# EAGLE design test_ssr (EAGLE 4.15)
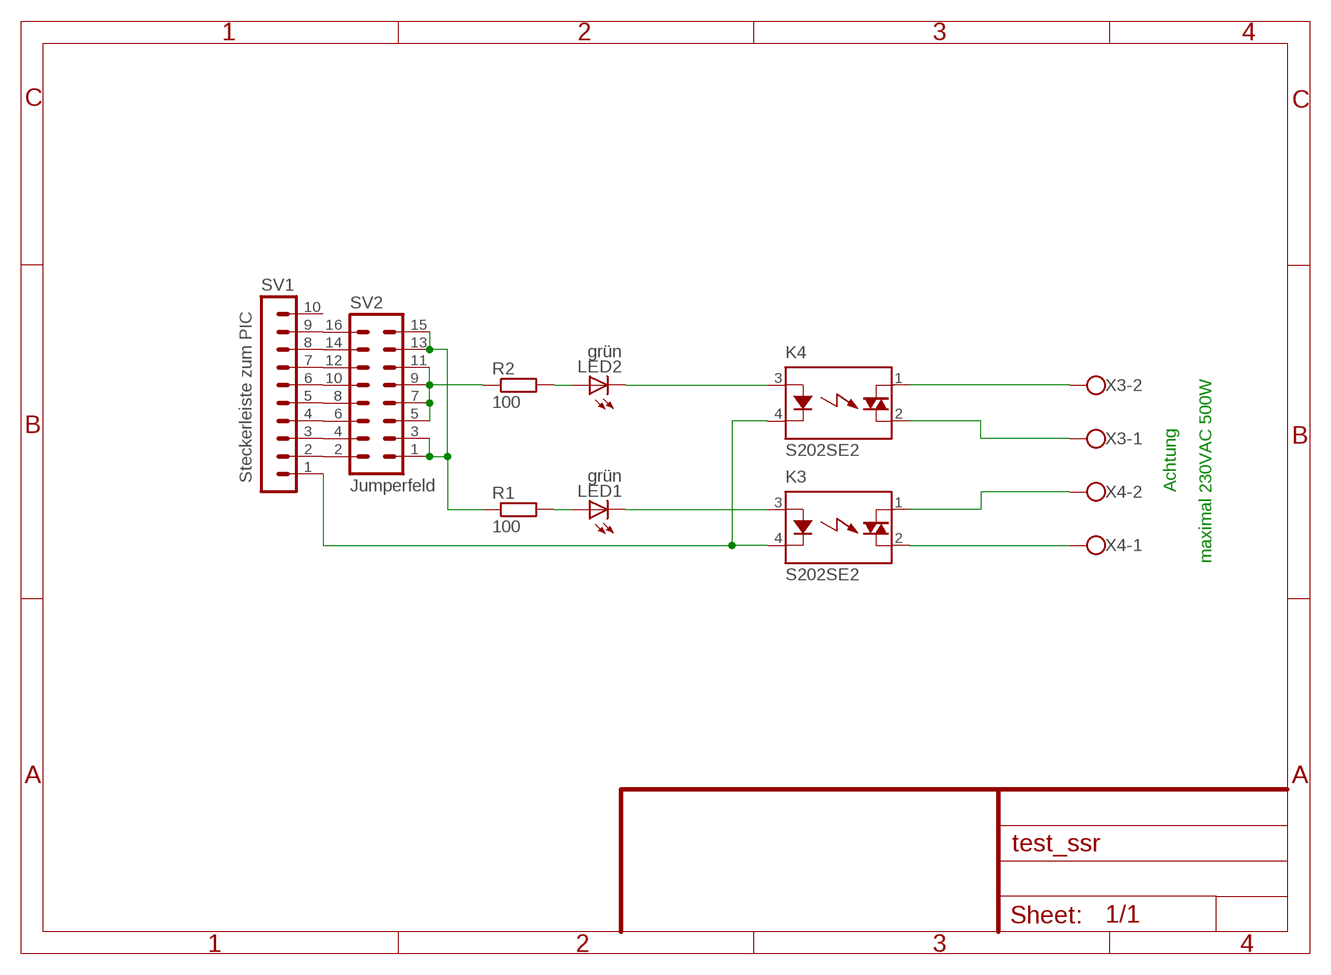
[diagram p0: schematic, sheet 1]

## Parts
K3  S202SE2  [S2XXEX]
K4  S202SE2  [S2XXEX]
LED1  grün  LED3MM  [LED3MM]
LED2  grün  LED3MM  [LED3MM]
R1  100  R-EU_0207/10  [0207/10]
R2  100  R-EU_0207/10  [0207/10]
SV1  Steckerleiste zum PIC  MA10-1W  [MA10-1W]
SV2  Jumperfeld  MA08-2  [MA08-2]
X3  W237-102  [W237-102]
X4  W237-102  [W237-102]

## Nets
GND: K3.4(K) K4.4(K) SV1.1
N$1: SV1.2 SV2.2
N$2: SV1.3 SV2.4
N$3: SV1.4 SV2.6
N$4: SV1.5 SV2.8
N$5: SV1.6 SV2.10
N$6: SV1.7 SV2.12
N$7: SV1.8 SV2.14
N$8: SV1.9 SV2.16
N$9: R1.1 SV2.1 SV2.3 SV2.13 SV2.15
N$10: R2.1 SV2.5 SV2.7 SV2.9 SV2.11
N$11: K4.2(DS2) X3.1
N$12: K4.3(A) LED2.K(C)
N$13: K3.3(A) LED1.K(C)
N$15: LED2.A R2.2
N$16: LED1.A R1.2
N$18: K4.1(DS1) X3.2
N$24: K3.1(DS1) X4.2
N$25: K3.2(DS2) X4.1
Unconnected: SV1.10

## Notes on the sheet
- Achtung
- maximal 230VAC 500W

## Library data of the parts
K3 K4 = relay:S2*: SIP Type SSR for Medium Power Control SHARP Source: 168149-da-01-en-Solid_State_Relais_S_202_SE1_SE2.pdf
LED1 LED2 = led:LED: LED
R1 R2 = rcl:R-EU_: RESISTOR, European symbol
SV1 = con-lstb:MA10-1W: PIN HEADER
SV2 = con-lstb:MA08-2: PIN HEADER
X3 X4 = con-wago-500:W237-102: WAGO SCREW CLAMP

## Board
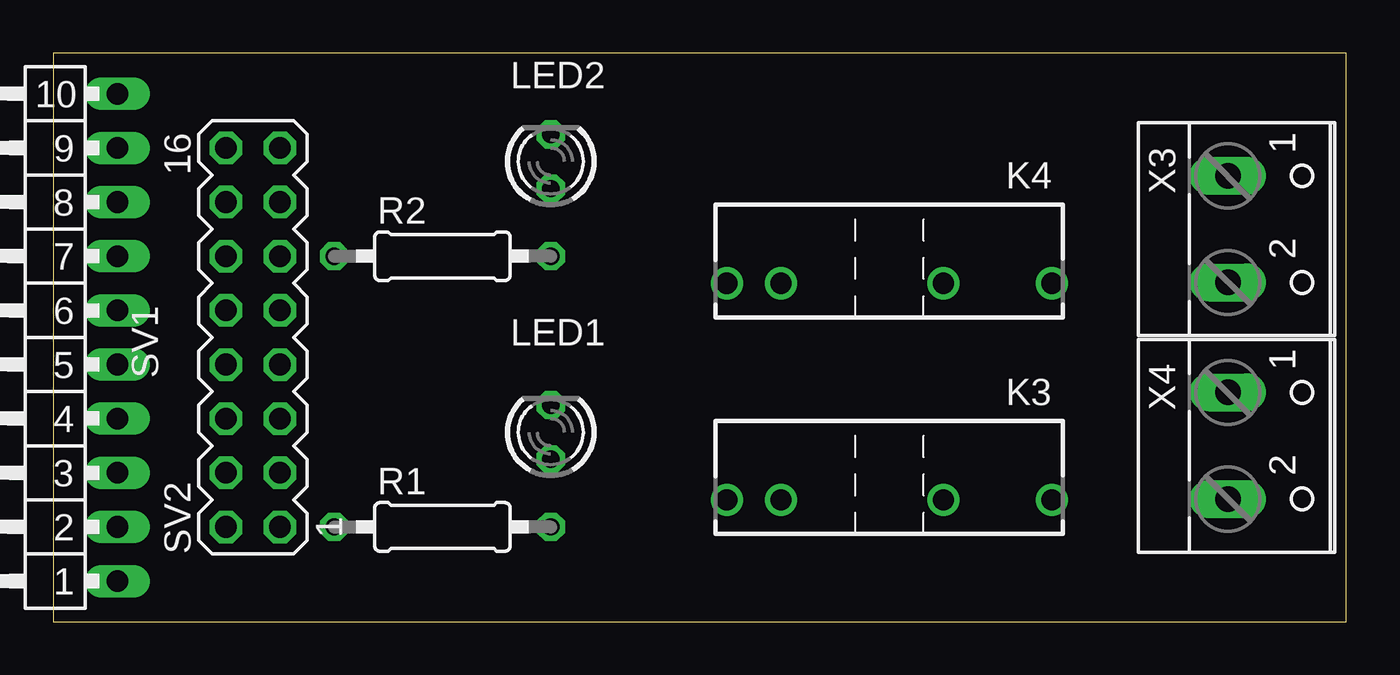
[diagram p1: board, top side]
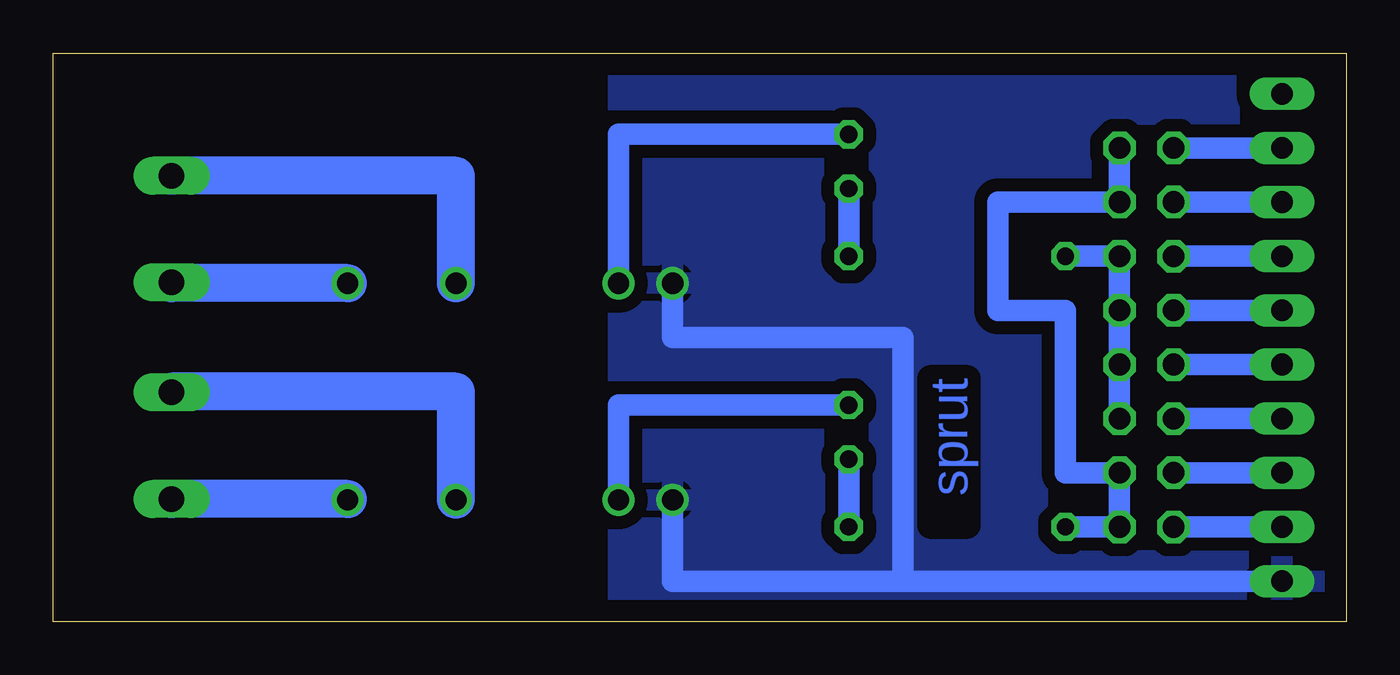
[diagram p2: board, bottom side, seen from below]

Size 60.63 x 26.66 mm. Coordinates in mm from the lower left corner, seen from the top.
Outline: 0,0 60.63,0 60.63,26.66 0,26.66 0,0
Copper layers (1*16): Top 0.035mm / dielectric 1.5mm / Bottom 0.035mm
Design rules "default": minimum track width 10mil, minimum drill 10mil, track to track 8mil, track to pad 8mil, pad to pad 8mil, via to via 8mil, smd to smd 8mil, copper to edge 40mil, drill to drill 8mil, minimum pad ring 10mil, minimum via ring 8mil, stop-mask expansion 4mil, vias tented up to drill 0mil, thermal gap 10mil

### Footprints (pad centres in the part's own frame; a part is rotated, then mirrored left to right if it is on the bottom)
S2XXEX = drill 1 round: 1 -7.62,0; 2 -2.54,0; 3 5.08,0; 4 7.62,0
LED3MM = drill 0.813 octagon: A -1.27,0; K 1.27,0
0207/10 = drill 0.813 octagon: 1 -5.08,0; 2 5.08,0
MA10-1W = drill 1.016 long: 1 -11.43,0; 2 -8.89,0; 3 -6.35,0; 4 -3.81,0; 5 -1.27,0; 6 1.27,0; 7 3.81,0; 8 6.35,0; 9 8.89,0; 10 11.43,0
MA08-2 = drill 1.016 octagon: 1 -8.89,-1.27; 2 -8.89,1.27; 3 -6.35,-1.27; 4 -6.35,1.27; 5 -3.81,-1.27; 6 -3.81,1.27; 7 -1.27,-1.27; 8 -1.27,1.27; 9 1.27,-1.27; 10 1.27,1.27; 11 3.81,-1.27; 12 3.81,1.27; 13 6.35,-1.27; 14 6.35,1.27; 15 8.89,-1.27; 16 8.89,1.27
W237-102 = drill 1.194 long: 1 -2.5,-1.27; 2 2.5,-1.27

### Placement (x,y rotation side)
K3  39.2,5.71 180 top
K4  39.2,15.87 180 top
LED1  23.33,8.88 90 top
LED2  23.33,21.59 90 top
R1  18.25,4.44 0 top
R2  18.25,17.14 0 top
SV1  3.01,13.33 90 top
SV2  9.36,13.33 90 top
X3  56.35,18.41 270 top
X4  56.35,8.25 270 top

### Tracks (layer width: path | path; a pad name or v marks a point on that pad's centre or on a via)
GND
  Bottom 1.016: SV1.1 20.79,1.9 | K4.4 31.58,13.33 20.79,13.33 20.79,1.9 | K3.4 31.58,1.9 20.79,1.9 | 20.79,1.9 20.15,1.9
  pour Bottom (isolate 0.61): -1.44,27.93 34.12,27.93 34.12,-1.27 -2.07,-1.27 -2.07,27.93
N$1
  Bottom 1.016: SV1.2 SV2.2
N$2
  Bottom 1.016: SV1.3 SV2.4
N$3
  Bottom 1.016: SV1.4 SV2.6
N$4
  Bottom 1.016: SV1.5 SV2.8
N$5
  Bottom 1.016: SV1.6 SV2.10
N$6
  Bottom 1.016: SV1.7 SV2.12
N$7
  Bottom 1.016: SV1.8 SV2.14
N$8
  Bottom 1.016: SV1.9 SV2.16
N$9
  Bottom 1.016: SV2.15 SV2.13 16.34,19.68 16.34,14.6 13.17,14.6 13.17,6.98 SV2.3 SV2.1 R1.1
N$10
  Bottom 1.016: SV2.5 SV2.7 SV2.9 SV2.11 R2.1
N$11
  Bottom 0.406: 41.74,20.91 41.74,20.95
  Bottom 1.778: X3.1 41.74,20.91 K4.2
N$12
  Bottom 1.016: LED2.K 34.12,22.85 K4.3
N$13
  Bottom 1.016: LED1.K 34.12,10.16 K3.3
N$15
  Bottom 1.016: R2.2 LED2.A
N$16
  Bottom 1.016: R1.2 LED1.A
N$18
  Bottom 0.406: 55.08,15.87 X3.2
  Bottom 1.778: K4.1 55.08,15.87
N$24
  Bottom 1.016: K3.1 46.82,5.75
  Bottom 1.778: 46.82,5.75 X4.2
N$25
  Bottom 0.406: 55.08,10.79 X4.1
  Bottom 1.778: K3.2 41.74,10.79 55.08,10.79

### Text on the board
Bottom: sprut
